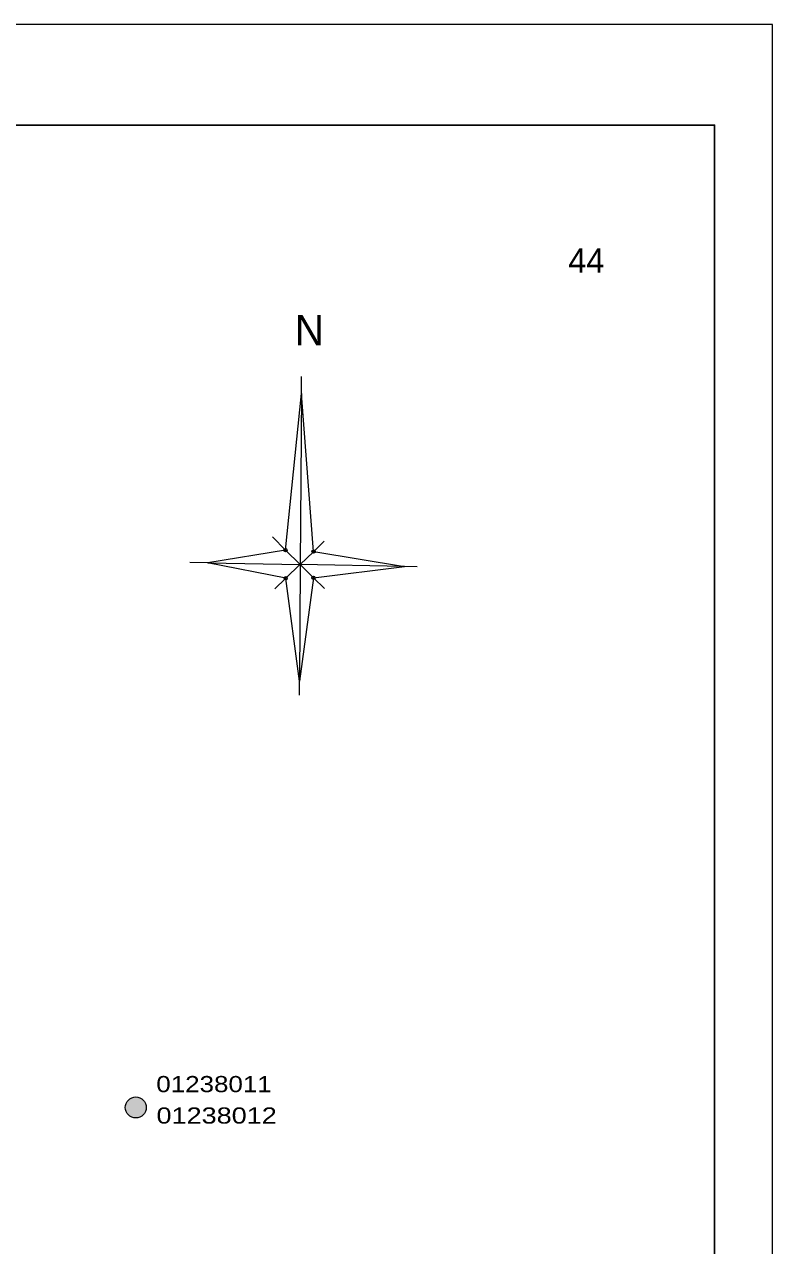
# Model space of a CAD drawing. Extents: x 854879 to 917879, y 8541948 to 8631048.
# Drawn here: x 899370 to 917879, y 8600845 to 8631048 of the extents above; entities that cross this region are included whole.
import ezdxf
from ezdxf.enums import TextEntityAlignment as Align

# ---------------------------------------------------------------- set-up
doc = ezdxf.new("R2010")
doc.units = 0
doc.header["$LTSCALE"] = 160
doc.header["$PDMODE"] = 32
doc.header["$PDSIZE"] = 80
for name, color, linetype, lineweight in [('1', 7, 'Continuous', 13), ('18', 7, 'Continuous', 13), ('36', 7, 'Continuous', 13), ('44', 7, 'Continuous', 13), ('50', 7, 'Continuous', 13), ('53', 7, 'Continuous', 13), ('63', 7, 'Continuous', 13)]:
    doc.layers.add(name, color=color, linetype=linetype, lineweight=lineweight)

msp = doc.modelspace()

# ---------------------------------------------------------------- hatches: boundary and pattern name
at = {"layer": '1'}
msp.add_hatch(color=256, dxfattribs=at).paths.add_polyline_path([(902386, 8604260.6, 1), (901865.6, 8604260.6, 1)])

# ---------------------------------------------------------------- linework, layer by layer
msp.add_circle((902125.8, 8604260.6), 260.2, dxfattribs=at)
at = {"layer": '18'}
msp.add_lwpolyline([(858846.4, 8601455.3), (858846.4, 8628560.7), (916445.6, 8628560.7), (916445.6, 8586757.5), (916451.2, 8586745.1)], dxfattribs=at)
at = {"layer": '36'}
msp.add_lwpolyline([(854878.6, 8541948.4), (917878.6, 8541948.4), (917878.6, 8631048.4), (854878.6, 8631048.4)], close=True, dxfattribs=at)
at = {"layer": '36', "lineweight": 25}
msp.add_lwpolyline([(858846.4, 8628560.7), (916445.6, 8628560.7), (916445.6, 8544954.2), (858846.4, 8544954.2)], close=True, dxfattribs=at)
at = {"layer": '44'}
msp.add_lwpolyline([(858846.4, 8628560.7), (916445.6, 8628560.7), (916445.6, 8544954.2), (858846.4, 8544954.2)], close=True, dxfattribs=at)
at = {"layer": '50'}
for p, q in [((906223.8, 8621918.9), (906226.8, 8622340.4)), ((906524.5, 8618010.5), (906224.2, 8621915.5)), ((905827.4, 8618047.1), (905508.3, 8618372.1)), ((905826.2, 8618046), (903904.5, 8617731.9)), ((906190.8, 8617689.8), (905828.7, 8618045.8)), ((906190.7, 8617690.4), (906521.5, 8618007.7)), ((906527.6, 8618013.6), (906788.4, 8618268.9)), ((906530.1, 8618009.6), (908774.2, 8617641.4)), ((903901.9, 8617731.7), (903465.8, 8617739.8)), ((905835.4, 8617349.8), (906186.9, 8617686.8)), ((908773.1, 8617641.3), (906193.4, 8617689.2)), ((906524, 8617363.6), (908773.8, 8617641.2)), ((909082.6, 8617635.6), (908774, 8617641.3)), ((905567, 8617092.4), (905831.9, 8617346.4)), ((906174.1, 8614808.7), (905834.6, 8617342.2)), ((906791, 8617099.8), (906523, 8617363.3)), ((906172.3, 8614457), (906174.7, 8614804.8))]:
    msp.add_line(p, q, dxfattribs=at)
for points in [[(905828.3, 8618048.2), (906223.8, 8621919.6), (906223.9, 8621918.9)], [(906223.8, 8621916.9), (906194.6, 8617689.2), (906190.7, 8617690.4)], [(905833.5, 8617350.3), (903903, 8617731.7), (903903.1, 8617731.7)], [(903906, 8617731.7), (906190.4, 8617689.3), (906190.8, 8617689.8)], [(906194.6, 8617683.7), (906174.7, 8614806.5), (906174.1, 8614808.7)], [(906191.8, 8617688.9), (906522.6, 8617363.7), (906524, 8617363.6)], [(906522.8, 8617363.4), (906520.9, 8617363.2), (906174.7, 8614804.3), (906174.6, 8614805.1)]]:
    msp.add_lwpolyline(points, dxfattribs=at)
for p in [(905828.1, 8618046.3), (906524.5, 8618010.5), (905833.5, 8617350.3), (906520.9, 8617363.2)]:
    msp.add_point(p, dxfattribs=at)

# ---------------------------------------------------------------- texts
at = {"layer": '1'}
for s, width, p in [('01238011', 1.2, (904060.5, 8604639.1)), ('01238012', 1.25, (904125.8, 8603861.8))]:
    msp.add_text(s, height=400, dxfattribs=dict(at, width=width)).set_placement(p, align=Align.CENTER)
at = {"layer": '53'}
msp.add_text('44', height=600, dxfattribs=at).set_placement((913270, 8624906.2), align=Align.CENTER)
at = {"layer": '63'}
msp.add_text('N', height=750, dxfattribs=at).set_placement((906420.2, 8623112.6), align=Align.CENTER)

doc.saveas('drawing.dxf')
